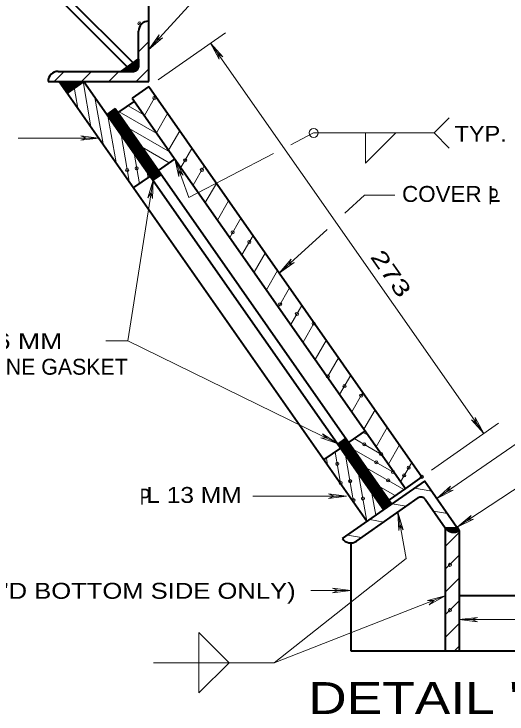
# Model space of a CAD drawing. Extents: x 312583 to 312854, y 144419 to 144597.
# Drawn here: x 312738.38 to 312761.89, y 144544.93 to 144578.31 of the extents above; entities that cross this region are included whole.
import ezdxf
from ezdxf.enums import TextEntityAlignment as Align

# ---------------------------------------------------------------- set-up
doc = ezdxf.new("R2010")
doc.units = 0
doc.header["$LTSCALE"] = 0.3
doc.header["$PDMODE"] = 32
doc.header["$PDSIZE"] = 0.15
doc.layers.add('1', color=7, linetype='Continuous', lineweight=13)

msp = doc.modelspace()

# ---------------------------------------------------------------- linework, layer by layer
at = {"layer": '1', "lineweight": 40}
for p, q in [((312744.802, 144575.0944), (312744.802, 144583.6044)), ((312739.0137, 144580.5607), (312743.7747, 144575.7997)), ((312739.282, 144580.7524), (312744.0584, 144575.9761)), ((312744.319, 144575.8151), (312744.319, 144577.4941)), ((312744.319, 144576.1677), (312743.4757, 144575.5774)), ((312740.4857, 144575.5774), (312744.0814, 144575.5774)), ((312740.0104, 144575.0944), (312744.802, 144575.0944)), ((312740.5394, 144575.0944), (312755.221, 144554.1184)), ((312741.7047, 144575.0944), (312740.9227, 144574.5424)), ((312741.7047, 144575.0944), (312756.0107, 144554.6704)), ((312744.802, 144574.8567), (312744.0124, 144574.3047)), ((312744.802, 144574.8567), (312757.8277, 144556.2421)), ((312744.1197, 144574.1514), (312743.3377, 144573.6071)), ((312744.0124, 144574.3047), (312757.0457, 144555.6901)), ((312743.1997, 144573.7987), (312742.8087, 144573.5227)), ((312743.1997, 144573.7987), (312756.4017, 144554.9464)), ((312743.238, 144573.7527), (312742.8394, 144573.4767)), ((312743.2687, 144573.6991), (312742.8777, 144573.4307)), ((312743.307, 144573.6531), (312742.9084, 144573.3771)), ((312743.3377, 144573.5994), (312742.9467, 144573.3311)), ((312743.3684, 144573.5534), (312742.9774, 144573.2774)), ((312743.4067, 144573.5074), (312743.0157, 144573.2314)), ((312743.4374, 144573.4537), (312743.0464, 144573.1854)), ((312743.4757, 144573.4077), (312743.0847, 144573.1317)), ((312743.5064, 144573.3541), (312743.1154, 144573.0857)), ((312743.5447, 144573.3081), (312743.1537, 144573.0321)), ((312743.5754, 144573.2621), (312743.1844, 144572.9861)), ((312743.6137, 144573.2084), (312743.2227, 144572.9324)), ((312743.6444, 144573.1624), (312743.2534, 144572.8864)), ((312743.6827, 144573.1087), (312743.284, 144572.8404)), ((312743.7134, 144573.0627), (312743.3224, 144572.7867)), ((312743.7517, 144573.0167), (312743.353, 144572.7407)), ((312743.7824, 144572.9631), (312743.3914, 144572.6871)), ((312743.8207, 144572.9171), (312743.422, 144572.6411)), ((312743.8514, 144572.8634), (312743.4604, 144572.5951)), ((312743.8897, 144572.8174), (312743.491, 144572.5414)), ((312743.9204, 144572.7714), (312743.5294, 144572.4954)), ((312743.951, 144572.7177), (312743.56, 144572.4417)), ((312743.9894, 144572.6717), (312743.5984, 144572.3957)), ((312744.02, 144572.6181), (312743.629, 144572.3497)), ((312744.0584, 144572.5721), (312743.6674, 144572.2961)), ((312744.089, 144572.5261), (312743.698, 144572.2501)), ((312744.1274, 144572.4724), (312743.7364, 144572.1964)), ((312744.158, 144572.4264), (312743.767, 144572.1504)), ((312744.1964, 144572.3727), (312743.7977, 144572.1044)), ((312744.227, 144572.3267), (312743.836, 144572.0507)), ((312744.2654, 144572.2731), (312743.8667, 144572.0047)), ((312744.296, 144572.2271), (312743.905, 144571.9511)), ((312744.3344, 144572.1811), (312743.9357, 144571.9051)), ((312744.365, 144572.1274), (312743.974, 144571.8591)), ((312744.4034, 144572.0814), (312744.0047, 144571.8054)), ((312744.434, 144572.0277), (312744.043, 144571.7594)), ((312744.4724, 144571.9817), (312744.0737, 144571.7057)), ((312744.503, 144571.9357), (312744.112, 144571.6597)), ((312744.5337, 144571.8821), (312744.1427, 144571.6061)), ((312744.572, 144571.8361), (312744.181, 144571.5601)), ((312744.6027, 144571.7824), (312744.2117, 144571.5141)), ((312744.641, 144571.7364), (312744.25, 144571.4604)), ((312744.6717, 144571.6904), (312744.2807, 144571.4144)), ((312744.71, 144571.6367), (312744.319, 144571.3607)), ((312744.7407, 144571.5907), (312744.3497, 144571.3147)), ((312744.779, 144571.5371), (312744.3804, 144571.2687)), ((312744.8097, 144571.4911), (312744.4187, 144571.2151)), ((312744.848, 144571.4451), (312744.4494, 144571.1691)), ((312744.8787, 144571.3914), (312744.4877, 144571.1154)), ((312744.917, 144571.3454), (312744.5184, 144571.0694)), ((312744.9477, 144571.2917), (312744.5567, 144571.0234)), ((312744.986, 144571.2457), (312744.5874, 144570.9697)), ((312745.0167, 144571.1997), (312744.6257, 144570.9237)), ((312745.0474, 144571.1461), (312744.6564, 144570.8701)), ((312746.044, 144571.4067), (312745.262, 144570.8547)), ((312745.0857, 144571.1001), (312744.6947, 144570.8241)), ((312745.1164, 144571.0464), (312744.7254, 144570.7781)), ((312745.1547, 144571.0004), (312744.7637, 144570.7244)), ((312745.1854, 144570.9467), (312744.7944, 144570.6784)), ((312745.2237, 144570.9007), (312744.8327, 144570.6247)), ((312745.2544, 144570.8547), (312744.8634, 144570.5787)), ((312745.2927, 144570.8011), (312744.9017, 144570.5327)), ((312744.871, 144570.5864), (312744.0814, 144570.0344)), ((312745.3234, 144570.7551), (312744.9324, 144570.4791)), ((312745.3617, 144570.7014), (312744.963, 144570.4331)), ((312745.4, 144570.6631), (312745.0014, 144570.3871)), ((312755.1214, 144558.4347), (312754.3394, 144557.8904)), ((312754.2014, 144558.0821), (312753.8104, 144557.8061)), ((312754.2397, 144558.0361), (312753.8487, 144557.7601)), ((312754.2704, 144557.9824), (312753.8794, 144557.7141)), ((312754.3087, 144557.9364), (312753.9177, 144557.6604)), ((312754.3394, 144557.8827), (312753.9484, 144557.6144)), ((312754.3777, 144557.8367), (312753.979, 144557.5607)), ((312754.4084, 144557.7907), (312754.0174, 144557.5147)), ((312753.9484, 144557.6144), (312753.1587, 144557.0624)), ((312754.4467, 144557.7371), (312754.048, 144557.4687)), ((312754.4774, 144557.6911), (312754.0864, 144557.4151)), ((312754.5157, 144557.6374), (312754.117, 144557.3691)), ((312754.5464, 144557.5914), (312754.1554, 144557.3154)), ((312754.5847, 144557.5454), (312754.186, 144557.2694)), ((312754.6154, 144557.4917), (312754.2244, 144557.2157)), ((312754.646, 144557.4457), (312754.255, 144557.1697)), ((312754.6844, 144557.3921), (312754.2934, 144557.1237)), ((312754.715, 144557.3461), (312754.324, 144557.0701)), ((312754.7534, 144557.3001), (312754.3624, 144557.0241)), ((312754.784, 144557.2464), (312754.393, 144556.9704)), ((312754.8224, 144557.2004), (312754.4314, 144556.9244)), ((312754.853, 144557.1467), (312754.462, 144556.8784)), ((312754.8914, 144557.1007), (312754.5004, 144556.8247)), ((312754.922, 144557.0547), (312754.531, 144556.7787)), ((312754.9604, 144557.0011), (312754.5617, 144556.7251)), ((312754.991, 144556.9551), (312754.6, 144556.6791)), ((312755.0294, 144556.9014), (312754.6307, 144556.6331)), ((312755.06, 144556.8554), (312754.669, 144556.5794)), ((312755.0984, 144556.8094), (312754.6997, 144556.5334)), ((312755.129, 144556.7557), (312754.738, 144556.4797)), ((312755.1674, 144556.7097), (312754.7687, 144556.4337)), ((312755.198, 144556.6561), (312754.807, 144556.3877)), ((312755.2287, 144556.6101), (312754.8377, 144556.3341)), ((312755.267, 144556.5564), (312754.876, 144556.2881)), ((312755.2977, 144556.5104), (312754.9067, 144556.2344)), ((312755.336, 144556.4644), (312754.945, 144556.1884)), ((312755.3667, 144556.4107), (312754.9757, 144556.1424)), ((312755.405, 144556.3647), (312755.014, 144556.0887)), ((312755.4357, 144556.3111), (312755.0447, 144556.0427)), ((312755.474, 144556.2651), (312755.083, 144555.9891)), ((312755.5047, 144556.2191), (312755.1137, 144555.9431)), ((312755.543, 144556.1654), (312755.1444, 144555.8894)), ((312755.5737, 144556.1194), (312755.1827, 144555.8434)), ((312757.8277, 144556.2421), (312757.0457, 144555.6901)), ((312755.612, 144556.0657), (312755.2134, 144555.7974)), ((312755.6427, 144556.0197), (312755.2517, 144555.7437)), ((312755.681, 144555.9737), (312755.2824, 144555.6977)), ((312755.7117, 144555.9201), (312755.3207, 144555.6441)), ((312755.75, 144555.8741), (312755.3514, 144555.5981)), ((312755.7807, 144555.8204), (312755.3897, 144555.5521)), ((312755.8114, 144555.7744), (312755.4204, 144555.4984)), ((312755.8497, 144555.7284), (312755.4587, 144555.4524)), ((312755.8804, 144555.6747), (312755.4894, 144555.3987)), ((312755.9187, 144555.6287), (312755.5277, 144555.3527)), ((312755.9494, 144555.5751), (312755.5584, 144555.3067)), ((312755.9877, 144555.5291), (312755.5967, 144555.2531)), ((312756.0184, 144555.4831), (312755.6274, 144555.2071)), ((312757.0457, 144555.6901), (312756.2637, 144555.1381)), ((312754.7074, 144553.1754), (312757.6514, 144555.2377)), ((312756.0567, 144555.4294), (312755.658, 144555.1534)), ((312756.0874, 144555.3834), (312755.6964, 144555.1074)), ((312756.1257, 144555.3297), (312755.727, 144555.0614)), ((312756.1564, 144555.2837), (312755.7654, 144555.0077)), ((312756.1947, 144555.2301), (312755.796, 144554.9617)), ((312756.2254, 144555.1841), (312755.8344, 144554.9081)), ((312756.2637, 144555.1381), (312755.865, 144554.8621)), ((312757.9887, 144555.1764), (312758.947, 144553.8041)), ((312756.2944, 144555.0844), (312755.9034, 144554.8161)), ((312756.325, 144555.0384), (312755.934, 144554.7624)), ((312756.3634, 144554.9847), (312755.9724, 144554.7164)), ((312758.947, 144553.8041), (312758.947, 144547.9391)), ((312758.947, 144553.8041), (312759.614, 144553.6891)), ((312759.614, 144553.6891), (312759.614, 144547.9391)), ((312754.439, 144553.0987), (312754.439, 144547.9391)), ((312759.614, 144550.5764), (312775.507, 144550.5764)), ((312754.439, 144547.9391), (312765.1034, 144547.9391))]:
    msp.add_line(p, q, dxfattribs=at)
at = {"layer": '1'}
for p, q in [((312744.802, 144576.6124), (312745.3004, 144577.3254)), ((312744.802, 144576.6124), (312745.4614, 144577.1797)), ((312745.3004, 144577.3254), (312745.193, 144577.0494)), ((312745.4614, 144577.1797), (312745.193, 144577.0494)), ((312745.2544, 144575.1787), (312748.459, 144577.4174)), ((312744.319, 144576.5127), (312744.802, 144576.9957)), ((312760.787, 144558.3044), (312747.7537, 144576.9191)), ((312747.7537, 144576.9191), (312748.16, 144576.1524)), ((312747.7537, 144576.9191), (312748.3364, 144576.2751)), ((312748.16, 144576.1524), (312748.091, 144576.4361)), ((312748.3364, 144576.2751), (312748.091, 144576.4361)), ((312740.3017, 144575.0944), (312740.777, 144575.5774)), ((312741.5974, 144575.0944), (312742.0804, 144575.5774)), ((312742.9007, 144575.0944), (312743.3837, 144575.5774)), ((312744.204, 144575.0944), (312744.802, 144575.6924)), ((312741.4287, 144573.8217), (312741.2064, 144575.0944)), ((312742.0497, 144572.9324), (312741.674, 144575.0944)), ((312742.6247, 144572.1197), (312742.2414, 144574.3354)), ((312744.595, 144573.4767), (312745.124, 144574.3967)), ((312744.572, 144573.5074), (312743.8207, 144573.9367)), ((312745.193, 144572.6104), (312743.399, 144573.6531)), ((312745.17, 144572.6487), (312745.699, 144573.5611)), ((312743.2457, 144571.2304), (312742.8547, 144573.4537)), ((312758.418, 144572.6411), (312759.1387, 144573.3617)), ((312745.8217, 144571.7211), (312743.8667, 144572.8481)), ((312741.559, 144572.5031), (312741.835, 144572.3957)), ((312742.4254, 144572.3957), (312741.559, 144572.5031)), ((312743.8744, 144570.3411), (312743.4834, 144572.5644)), ((312745.7527, 144571.8131), (312746.2817, 144572.7331)), ((312752.668, 144572.6411), (312751.5794, 144572.0737)), ((312758.418, 144572.6411), (312752.668, 144572.6411)), ((312758.418, 144572.6411), (312759.1387, 144571.9204)), ((312738.5844, 144572.3957), (312742.4254, 144572.3957)), ((312741.559, 144572.2884), (312741.835, 144572.3957)), ((312742.4254, 144572.3957), (312741.559, 144572.2884)), ((312745.7757, 144571.2151), (312744.4877, 144571.9587)), ((312746.3354, 144570.9851), (312746.8644, 144571.8974)), ((312744.365, 144570.2107), (312744.1044, 144571.6751)), ((312750.759, 144571.6521), (312746.7187, 144569.5667)), ((312746.7187, 144569.5667), (312746.044, 144571.4067)), ((312746.044, 144571.4067), (312746.2434, 144570.5557)), ((312746.044, 144571.4067), (312746.4427, 144570.6247)), ((312746.2434, 144570.5557), (312746.2434, 144570.8471)), ((312746.4427, 144570.6247), (312746.2434, 144570.8471)), ((312746.918, 144570.1494), (312747.447, 144571.0694)), ((312744.779, 144570.5021), (312744.733, 144570.7627)), ((312745.009, 144570.3871), (312744.7637, 144569.5514)), ((312745.009, 144570.3871), (312744.9784, 144569.5131)), ((312747.5007, 144569.3214), (312748.0297, 144570.2337)), ((312744.7637, 144569.5514), (312744.917, 144569.8044)), ((312744.9784, 144569.5131), (312744.917, 144569.8044)), ((312755.0907, 144569.6741), (312754.1554, 144568.8077)), ((312756.5397, 144569.6741), (312755.0907, 144569.6741)), ((312748.0834, 144568.4857), (312748.6124, 144569.4057)), ((312748.666, 144567.6577), (312749.195, 144568.5777)), ((312753.312, 144568.0411), (312751.0274, 144565.9557)), ((312749.2487, 144566.8221), (312749.7777, 144567.7421)), ((312749.8314, 144565.9941), (312750.3604, 144566.9141)), ((312751.0274, 144565.9557), (312751.5947, 144566.6227)), ((312751.0274, 144565.9557), (312751.7404, 144566.4617)), ((312751.5947, 144566.6227), (312751.4644, 144566.3544)), ((312751.7404, 144566.4617), (312751.4644, 144566.3544)), ((312750.414, 144565.1661), (312750.943, 144566.0784)), ((312750.9967, 144564.3304), (312751.5257, 144565.2504)), ((312751.5794, 144563.5024), (312752.1084, 144564.4147)), ((312752.162, 144562.6667), (312752.691, 144563.5867)), ((312742.755, 144562.7204), (312743.813, 144562.7204)), ((312752.7447, 144561.8387), (312753.2737, 144562.7511)), ((312753.3274, 144561.0031), (312753.8564, 144561.9231)), ((312753.91, 144560.1751), (312754.439, 144561.0951)), ((312754.485, 144559.3394), (312755.0217, 144560.2594)), ((312755.0677, 144558.5114), (312755.5967, 144559.4314)), ((312758.2877, 144556.5641), (312761.4924, 144558.8027)), ((312760.1967, 144558.9561), (312760.442, 144558.7874)), ((312760.787, 144558.3044), (312760.1967, 144558.9561)), ((312760.373, 144559.0787), (312760.442, 144558.7874)), ((312760.787, 144558.3044), (312760.373, 144559.0787)), ((312755.6504, 144557.6757), (312756.1794, 144558.5957)), ((312753.0054, 144558.1051), (312753.2967, 144558.0821)), ((312753.8334, 144557.8214), (312753.0054, 144558.1051)), ((312753.0974, 144558.2967), (312753.2967, 144558.0821)), ((312753.8334, 144557.8214), (312753.0974, 144558.2967)), ((312755.2824, 144558.2124), (312755.0294, 144558.3581)), ((312755.9034, 144557.3154), (312754.6, 144558.0667)), ((312756.5244, 144556.4261), (312754.5694, 144557.5531)), ((312756.233, 144556.8477), (312756.762, 144557.7677)), ((312753.335, 144556.8247), (312753.2814, 144557.1161)), ((312753.956, 144555.9354), (312753.6954, 144557.4227)), ((312754.577, 144555.0461), (312754.186, 144557.2694)), ((312756.8157, 144556.0121), (312757.3447, 144556.9321)), ((312756.969, 144555.6364), (312755.198, 144556.6637)), ((312755.2134, 144554.1337), (312754.8147, 144556.3801)), ((312758.5484, 144555.2071), (312759.2, 144555.7897)), ((312759.2, 144555.7897), (312759.039, 144555.5444)), ((312762.8417, 144556.0274), (312759.5144, 144553.8347)), ((312755.6274, 144554.4097), (312755.4434, 144555.4447)), ((312756.555, 144555.3451), (312755.8574, 144555.7514)), ((312757.4827, 144555.6977), (312758.3107, 144555.5521)), ((312758.5484, 144555.2071), (312759.3227, 144555.6134)), ((312759.3227, 144555.6134), (312759.039, 144555.5444)), ((312749.7624, 144555.3221), (312754.2397, 144555.3221)), ((312753.3734, 144555.4294), (312753.6494, 144555.3221)), ((312754.2397, 144555.3221), (312753.3734, 144555.4294)), ((312753.3734, 144555.2147), (312753.6494, 144555.3221)), ((312754.2397, 144555.3221), (312753.3734, 144555.2147)), ((312756.417, 144554.9541), (312757.084, 144554.8391)), ((312757.084, 144552.3474), (312756.6777, 144554.5554)), ((312756.6777, 144554.5554), (312756.7314, 144553.6814)), ((312756.6777, 144554.5554), (312756.9384, 144553.7197)), ((312758.3874, 144554.6091), (312759.0544, 144554.4864)), ((312755.3437, 144554.2104), (312756.0184, 144554.0877)), ((312759.5144, 144553.8347), (312760.1814, 144554.4021)), ((312759.5144, 144553.8347), (312760.2964, 144554.2181)), ((312760.1814, 144554.4021), (312760.005, 144554.1567)), ((312760.2964, 144554.2181), (312760.005, 144554.1567)), ((312756.7314, 144553.6814), (312756.785, 144553.9727)), ((312756.9384, 144553.7197), (312756.785, 144553.9727)), ((312754.278, 144553.4591), (312754.9527, 144553.3441)), ((312758.947, 144552.9147), (312759.614, 144553.5817)), ((312758.947, 144551.8337), (312759.614, 144552.5007)), ((312758.947, 144550.7451), (312759.614, 144551.4121)), ((312752.5377, 144550.8217), (312754.439, 144550.8217)), ((312753.5727, 144550.9291), (312753.8487, 144550.8217)), ((312754.439, 144550.8217), (312753.5727, 144550.9291)), ((312753.5727, 144550.7144), (312753.8487, 144550.8217)), ((312754.439, 144550.8217), (312753.5727, 144550.7144)), ((312750.7897, 144547.3794), (312758.947, 144550.5611)), ((312758.947, 144550.5611), (312758.1037, 144550.3464)), ((312758.947, 144550.5611), (312758.1804, 144550.1471)), ((312758.1037, 144550.3464), (312758.4027, 144550.3464)), ((312758.1804, 144550.1471), (312758.4027, 144550.3464)), ((312758.947, 144549.6641), (312759.614, 144550.3311)), ((312759.614, 144549.4341), (312760.4804, 144549.5414)), ((312765.939, 144549.4341), (312759.614, 144549.4341)), ((312759.614, 144549.4341), (312760.4804, 144549.3267)), ((312760.4804, 144549.5414), (312760.2044, 144549.4341)), ((312760.4804, 144549.3267), (312760.2044, 144549.4341)), ((312758.947, 144548.5754), (312759.614, 144549.2424)), ((312759.3917, 144547.9391), (312759.614, 144548.1614))]:
    msp.add_line(p, q, dxfattribs=at)
for points in [[(312748.3134, 144579.0657), (312747.033, 144579.0657), (312744.802, 144576.6124)], [(312756.5857, 144572.6411), (312755.1444, 144571.1997), (312755.1444, 144572.6411)], [(312745.009, 144570.3871), (312743.813, 144562.7204), (312753.8334, 144557.8214)], [(312763.2174, 144557.9977), (312762.5887, 144557.9977), (312758.5484, 144555.2071)], [(312745.0397, 144547.3794), (312750.7897, 144547.3794), (312757.084, 144552.3474)], [(312748.6354, 144547.3794), (312747.194, 144548.8207), (312747.194, 144547.3794)], [(312748.6354, 144547.3794), (312747.194, 144545.9457), (312747.194, 144547.3794)]]:
    msp.add_lwpolyline(points, dxfattribs=at)
at = {"layer": '1', "lineweight": 40}
for points in [[(312744.319, 144576.1524), (312744.3114, 144575.7997), (312744.2884, 144575.7231), (312744.25, 144575.6617), (312744.2117, 144575.6234), (312744.112, 144575.5927), (312743.5064, 144575.5851), (312744.3037, 144576.1524), (312744.3037, 144575.7997), (312744.2424, 144575.6617), (312744.112, 144575.6081), (312743.5294, 144575.5927), (312744.3037, 144576.1294), (312744.2807, 144575.7997), (312744.2194, 144575.6771), (312744.1044, 144575.6234), (312743.583, 144575.6081), (312744.2807, 144576.0987), (312744.2194, 144575.6924), (312743.6444, 144575.6234), (312744.2577, 144576.0757), (312744.2117, 144575.7077), (312743.698, 144575.6387), (312744.2424, 144576.0451), (312744.1964, 144575.7154), (312743.7594, 144575.6694), (312744.227, 144576.0221), (312744.181, 144575.7384), (312743.8207, 144575.6924), (312744.204, 144575.9837), (312744.1734, 144575.7537), (312743.8667, 144575.7077), (312744.1887, 144575.9607), (312744.158, 144575.7691), (312743.9204, 144575.7231), (312744.1657, 144575.9301), (312744.1504, 144575.7767), (312743.9664, 144575.7461), (312744.1504, 144575.8994), (312744.1427, 144575.7921), (312743.997, 144575.7614), (312744.135, 144575.8687), (312744.135, 144575.7997), (312744.043, 144575.7767), (312744.112, 144575.8227), (312744.1197, 144575.8151)], [(312744.2884, 144576.0757), (312744.2654, 144575.8151), (312744.2347, 144575.7077), (312744.112, 144575.6541), (312743.7364, 144575.6234)], [(312741.674, 144575.0791), (312740.5624, 144575.0791), (312740.9227, 144574.5654), (312741.651, 144575.0714), (312740.5854, 144575.0714), (312740.9304, 144574.5884), (312741.5974, 144575.0561), (312740.616, 144575.0484), (312740.9304, 144574.6191), (312741.536, 144575.0254), (312740.6544, 144575.0331), (312740.9304, 144574.6727), (312741.4594, 144575.0177), (312740.708, 144575.0177), (312740.938, 144574.7111), (312741.3904, 144574.9947), (312740.7617, 144574.9947), (312740.9457, 144574.7494), (312741.2984, 144574.9717), (312740.8077, 144574.9717), (312740.9457, 144574.7877), (312741.2217, 144574.9487), (312740.8384, 144574.9487), (312740.9534, 144574.8184), (312741.1527, 144574.9334), (312740.8844, 144574.9334), (312740.9534, 144574.8491), (312741.076, 144574.9104), (312740.9227, 144574.9181), (312740.961, 144574.8721), (312741.007, 144574.8951), (312740.9534, 144574.8951)], [(312754.0404, 144553.2981), (312757.9657, 144556.0427), (312759.614, 144553.6891)], [(312758.9547, 144553.8041), (312759.522, 144553.8194), (312759.5987, 144553.6891), (312759.5604, 144553.6661), (312759.4224, 144553.6201), (312759.2844, 144553.6201), (312759.177, 144553.6431), (312759.0774, 144553.7044), (312758.97, 144553.7964), (312759.5144, 144553.8117), (312759.5834, 144553.6967), (312759.5144, 144553.6661), (312759.407, 144553.6584), (312759.315, 144553.6431), (312759.246, 144553.6507), (312759.1847, 144553.6737), (312759.1234, 144553.7197), (312759.0774, 144553.7504), (312759.039, 144553.7734), (312759.016, 144553.7887), (312759.5067, 144553.8041), (312759.5527, 144553.7044), (312759.4914, 144553.6891), (312759.384, 144553.6891), (312759.2997, 144553.6814), (312759.2537, 144553.6814), (312759.1847, 144553.7121), (312759.1387, 144553.7427), (312759.1004, 144553.7657), (312759.0697, 144553.7734), (312759.4914, 144553.7887), (312759.5144, 144553.7121), (312759.4607, 144553.7044), (312759.361, 144553.7121), (312759.315, 144553.7121), (312759.269, 144553.7121), (312759.2154, 144553.7274), (312759.177, 144553.7504), (312759.1387, 144553.7657), (312759.4837, 144553.7734), (312759.4914, 144553.7274), (312759.407, 144553.7274), (312759.315, 144553.7351), (312759.269, 144553.7427), (312759.223, 144553.7504), (312759.3227, 144553.7581), (312759.4454, 144553.7657), (312759.4684, 144553.7657), (312759.4684, 144553.7504), (312759.315, 144553.7427)], [(312759.0084, 144553.7811), (312759.0697, 144553.7351), (312759.1387, 144553.6891), (312759.2, 144553.6507), (312759.2767, 144553.6354), (312759.3457, 144553.6277), (312759.4377, 144553.6431), (312759.522, 144553.6584)], [(312759.5374, 144553.6891), (312759.4684, 144553.6814), (312759.3534, 144553.6737), (312759.2844, 144553.6661), (312759.2, 144553.6814), (312759.1157, 144553.7427), (312759.0774, 144553.7657)], [(312759.1157, 144553.7581), (312759.1924, 144553.7351), (312759.223, 144553.7121), (312759.2767, 144553.6967), (312759.338, 144553.6967), (312759.4147, 144553.6967), (312759.4914, 144553.6967)], [(312759.2077, 144553.7504), (312759.2537, 144553.7351), (312759.292, 144553.7274)]]:
    msp.add_lwpolyline(points, dxfattribs=at)
at = {"layer": '1'}
msp.add_circle((312752.668, 144572.6411), 0.2123, dxfattribs=at)
at = {"layer": '1', "lineweight": 40}
for centre, radius, start, end in [((312744.7982, 144577.4922), 0.4792, 90, 180), ((312744.0795, 144575.8151), 0.2396, 270, 0), ((312740.4857, 144575.0963), 0.4792, 90, 180), ((312757.791, 144555.0415), 0.2396, 34.96634, 124.96634), ((312759.3412, 144554.0791), 0.4792, 214.96634, 304.96634), ((312754.4341, 144553.571), 0.4792, 214.96634, 304.96634)]:
    msp.add_arc(centre, radius, start, end, dxfattribs=at)
at = {"layer": '1'}
for p in [(312744.365, 144577.8621), (312745.0704, 144574.3047), (312746.5424, 144571.3377), (312743.7747, 144570.8701), (312744.227, 144570.9544), (312747.3397, 144570.8777), (312748.804, 144567.9031), (312749.6014, 144567.4431), (312751.0734, 144564.4684), (312751.8707, 144564.0084), (312752.668, 144563.5484), (312753.3427, 144561.0337), (312754.14, 144560.5737), (312754.9374, 144560.1137), (312755.0907, 144557.7907), (312755.888, 144557.3307), (312753.795, 144556.8631), (312755.658, 144556.9321), (312756.4554, 144556.4721), (312757.199, 144556.6791), (312754.4084, 144556.0351), (312756.2254, 144556.0734), (312756.9844, 144556.3111), (312757.8277, 144556.2421), (312753.956, 144555.9507), (312754.5694, 144555.1304), (312755.0217, 144555.2071), (312759.1694, 144552.0484), (312759.1694, 144549.8864)]:
    msp.add_point(p, dxfattribs=at)

# ---------------------------------------------------------------- texts
for s, width, p in [('TYP.', 1.1, (312759.3917, 144572.2184)), ('COVER L', 1.05, (312756.8847, 144569.3511)), ('P', 0.7, (312761.0068, 144569.2323)), ('32 BY 6 MM', 1.25, (312733.6936, 144562.3313)), ('L 13 MM', 1.15, (312744.6885, 144554.9991)), ('P', 0.7, (312744.3911, 144554.9196)), ("L 6 MM (3 REQ'D BOTTOM SIDE ONLY)", 1.2, (312729.4197, 144550.4278))]:
    msp.add_text(s, height=0.76, dxfattribs=dict(at, width=width)).set_placement(p)
at = {"layer": '1', "width": 1.45}
msp.add_text('273 ', height=0.76, rotation=304.998, dxfattribs=at).set_placement((312755.3415, 144566.7276))
at = {"layer": '1'}
msp.add_text('NEOPRENE GASKET', height=0.76, dxfattribs=at).set_placement((312733.6936, 144561.1113))
at = {"layer": '1', "width": 1.25}
msp.add_text('DETAIL "A"', height=1.52, dxfattribs=at).set_placement((312758.9593, 144544.934), align=Align.CENTER)

doc.saveas('drawing.dxf')
